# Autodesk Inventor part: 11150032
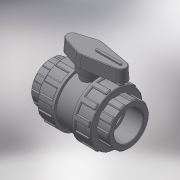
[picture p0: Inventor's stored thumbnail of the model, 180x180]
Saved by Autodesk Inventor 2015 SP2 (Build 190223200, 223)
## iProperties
Created: 2017-11
Part Number: 11150032
Material: Generic
Description: PLASSON 2/NUT VALVE CEM. PVC 32
Document SubType Name: Modeling
Designer: KIM
Density: 1 g/cm^3
Appearance: Default
Author: KIM
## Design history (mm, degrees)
derived "111500.ipt"
feature "Solid1::111500.ipt"
tag "TaggingFeature1"
body "Solid1"
other parameters: "d0" = 102, "d1" = 32, "d2" = 66, "d3" = 22, "d4" = 25.6, "d5" = 15.4, "d7" = 44.8, "d8" = 59.4, "d13" = 0.96, "d23" = 22, "d24" = 63.36, "d25" = 0.64, "d26" = 0.96, "d27" = 9.9, "d28" = 4.95, "d29" = 16.5, "d30" = 0, "d35" = 0.96, "d39" = 33, "d45" = 360 deg, "d47" = 0.64, "d50" = 36.3, "d51" = 19.8, "d53" = 0, "d55" = 6.4, "d56" = 3.2, "d57" = 15.4, "d58" = 0, "d59" = 0.96, "d61" = 360 deg, "d63" = 26.4, "d64" = 66, "d66" = 78, "d68" = 13.2, "d69" = 23.4, "d70" = 16.5, "d71" = 3 deg, "d73" = 1.32, "d74" = 31.2, "d75" = 1.98, "d76" = 0, "d77" = 0.64, "d_" = 32, "l_" = 22, "H_" = 102, "K_" = 66, "F_" = 66, "J_" = 78, "d67" = 26.4, "d72" = 6.6
